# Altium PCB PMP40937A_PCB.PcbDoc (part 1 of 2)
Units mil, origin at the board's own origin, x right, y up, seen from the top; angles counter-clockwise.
Board outline 1377.95 x 1377.95 mil, 2 copper layers (Top Layer, Bottom Layer), stack 62 mil thick; 90 components, 42 nets, 235 pads, 300 vias.
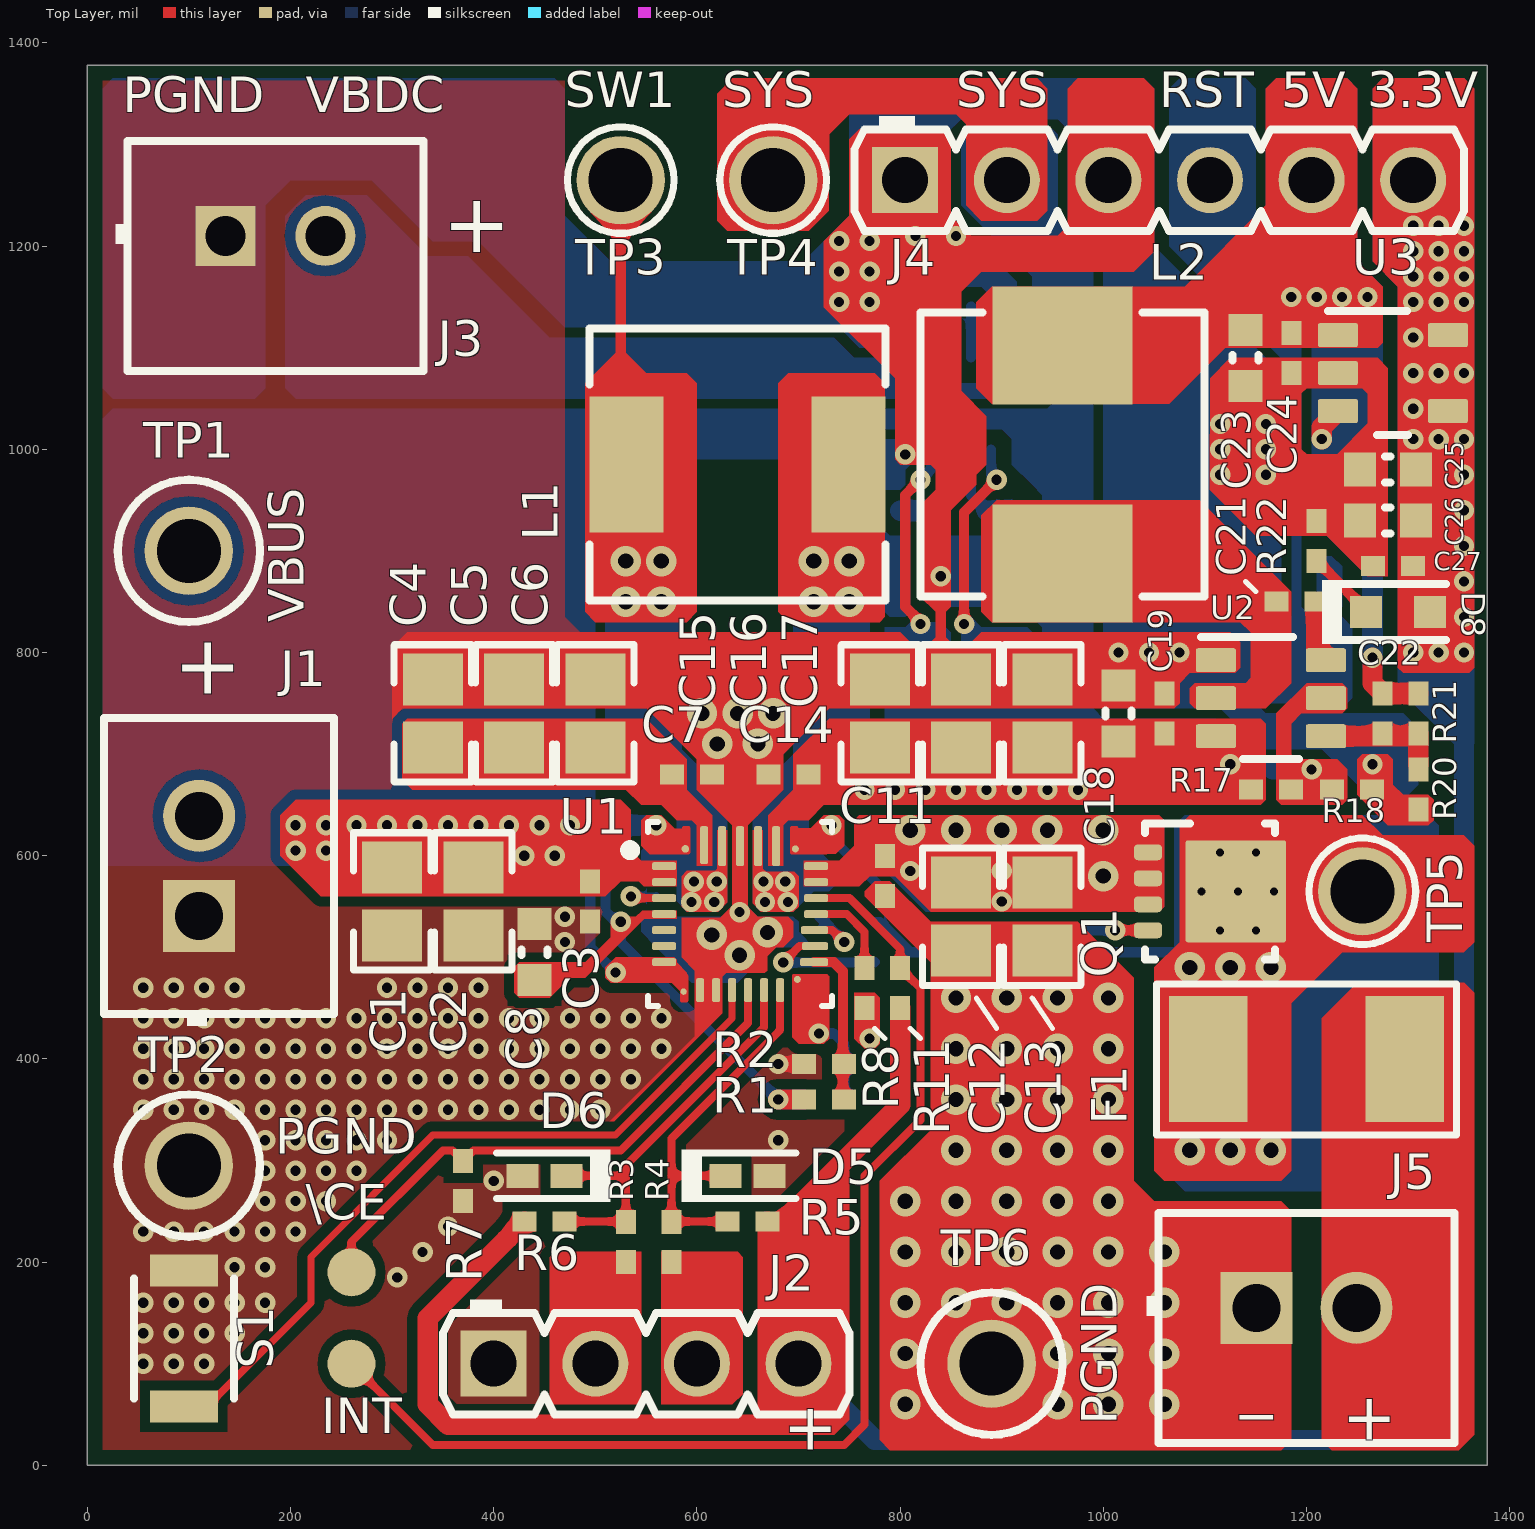
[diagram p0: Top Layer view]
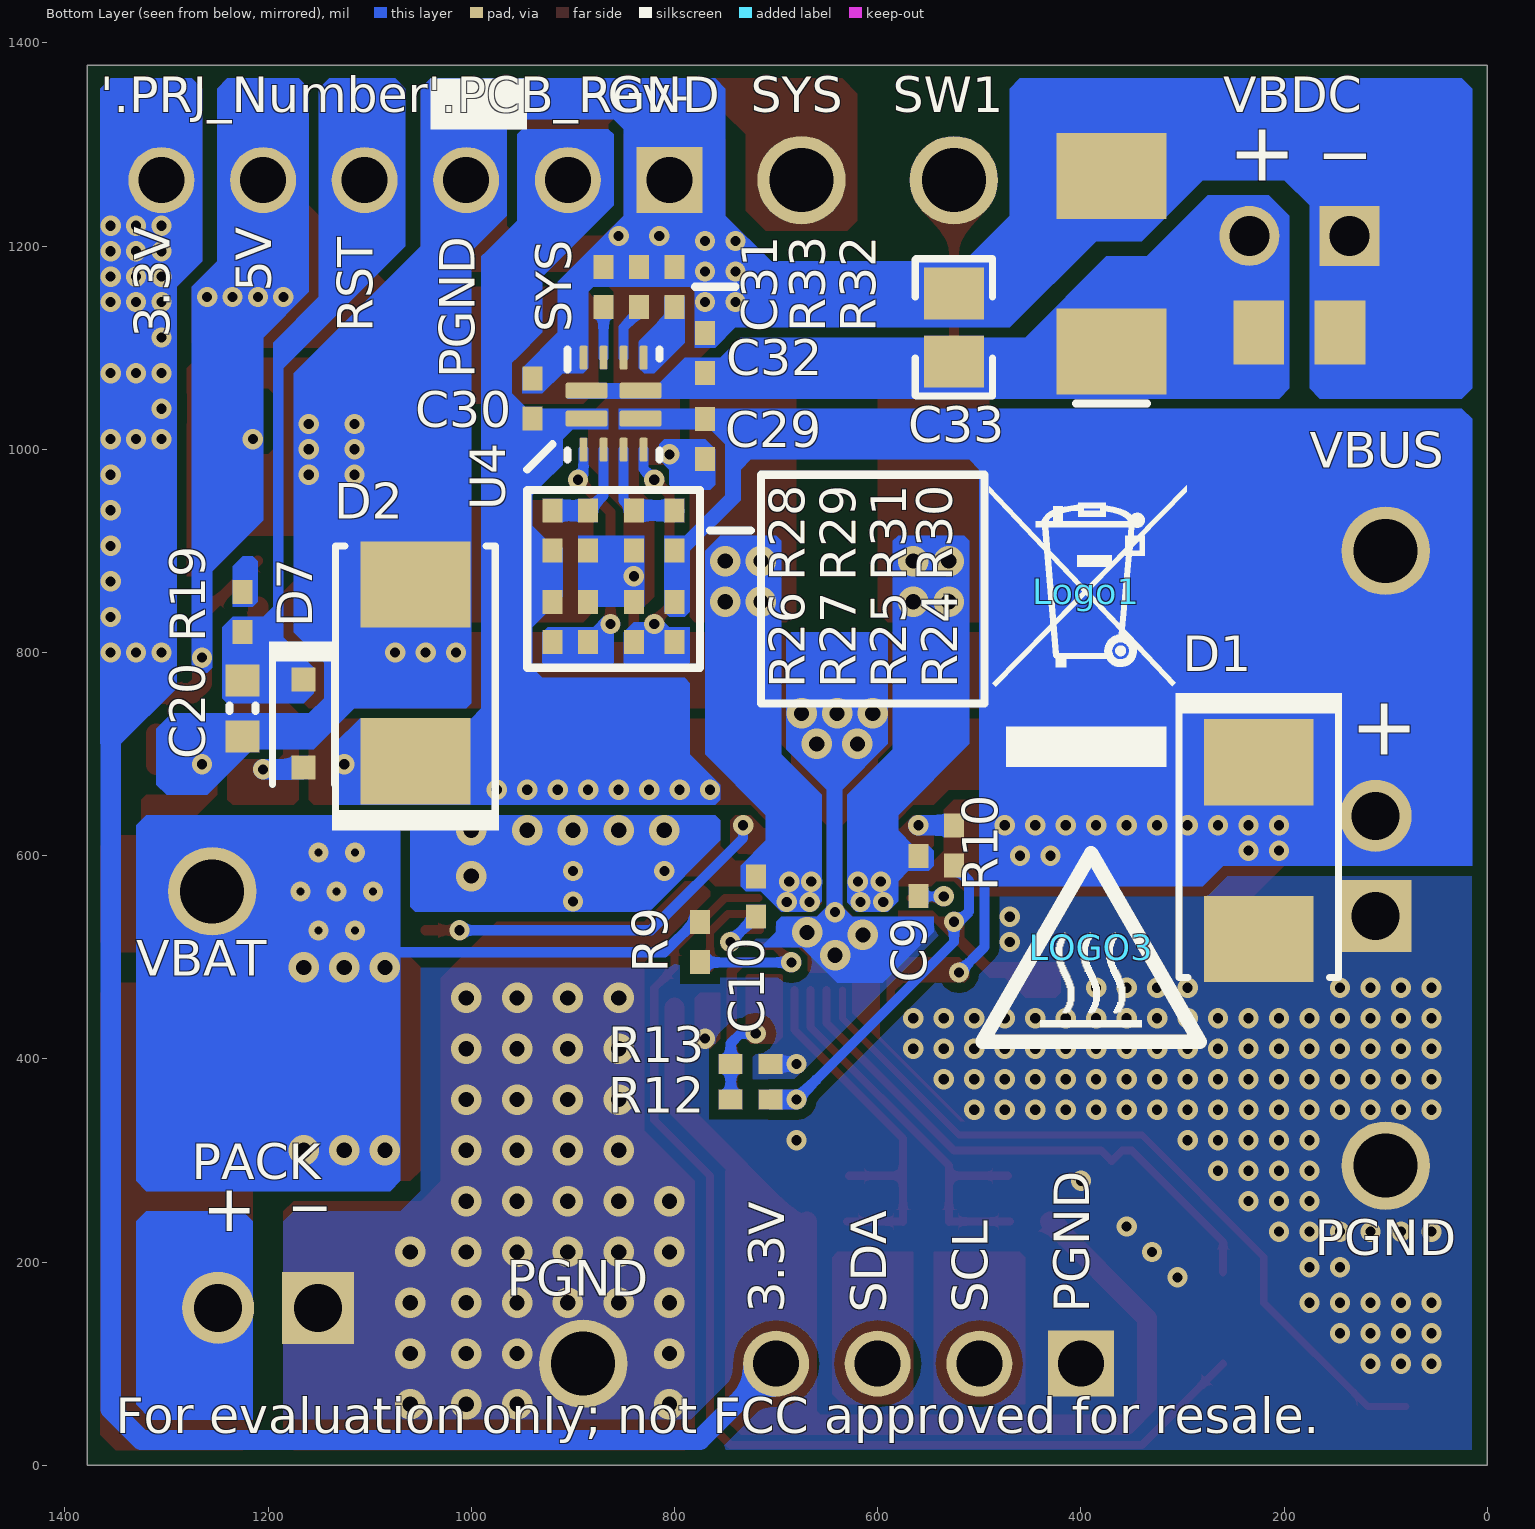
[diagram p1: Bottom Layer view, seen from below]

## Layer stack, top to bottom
Top Solder: solder mask 0.4, Solder Resist, Dk 3.5
Top Layer: signal copper 1.4
Dielectric1: core 59.2, FR-4, Dk 4.8
Bottom Layer: signal copper 1.4
Bottom Solder: solder mask 0.4, Solder Resist, Dk 3.5

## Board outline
0,0 1377.95,0 1377.95,1377.95 0,1377.95

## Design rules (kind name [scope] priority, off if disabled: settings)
AcuteAngle [All] p1: minimum=4.50000000000000E+0001 checktracksonly=FALSE
AssemblyTestPointUsage [All] p1: valid=2
BoardOutlineClearance [OnCopper and Not InComponentClass('Logo') and not InComponentClass('FiducialMark') and not InRegion(1000,500,4000,800)] p1: gap=15 ignorepadtopadclearanceinfootprint=FALSE
BoardOutlineClearance BoardOutlineClearance_MountingHoles [OnCopper and InComponentClass('Mounting Holes')] p2: gap=40 ignorepadtopadclearanceinfootprint=FALSE
BoardOutlineClearance BoardOutlineClearance_Poly [OnCopper and (  InNamedPolygon('Bottom Layer-AGND') or  InNamedPolygon('Signal Layer 1-PGND') or  InNamedPolygon('Signal Layer 2-AGND') or   InNamedPolygon('Top Layer-PGND') )] p3: gap=25 ignorepadtopadclearanceinfootprint=FALSE
Clearance Clearance_FID [IsPad and InComponentClass('FiducialMark') vs IsKeepOut and InComponentClass('FiducialMark')] p1: gap=0 ignorepadtopadclearanceinfootprint=FALSE
Clearance Clearance_2 [InNamedPolygon('Signal Layer 2 - AGND') or InNamedPolygon('Top Layer-PGND')] p2 off: gap=10 ignorepadtopadclearanceinfootprint=FALSE except(0: Arc-Hole Track-Hole SMDPad-Hole THPad-Hole Via-Hole Fill-Hole Poly-Hole Region-Hole Text-Hole; 25: Fill-Fill Fill-Poly Fill-Region Poly-Poly Poly-Region Region-Region)
Clearance "Poly Clearance" [InNamedPolygon('Signal Layer 1-PGND') Or  InNamedPolygon('Top Layer-PGND') Or  InNamedPolygon('Bottom Layer-AGND') Or  InNamedPolygon('Signal Layer 2-AGND')] p3 off: gap=10 ignorepadtopadclearanceinfootprint=FALSE except(0: Arc-Hole Track-Hole SMDPad-Hole THPad-Hole Via-Hole Fill-Hole Poly-Hole Region-Hole Text-Hole)
Clearance Clearance_U1_Top [TouchesRoom('U1_CSP_Top')] p4: gap=2.5 ignorepadtopadclearanceinfootprint=TRUE except(0: Arc-Hole Track-Hole SMDPad-Hole THPad-Hole Via-Hole Fill-Hole Poly-Hole Region-Hole Text-Hole)
Clearance Clearance_U1_Bottom [TouchesRoom('U1_CSP_Bottom')] p5: gap=2.5 ignorepadtopadclearanceinfootprint=TRUE except(0: Arc-Hole Track-Hole SMDPad-Hole THPad-Hole Via-Hole Fill-Hole Poly-Hole Region-Hole Text-Hole)
Clearance Clearance_1 [InNamedPolygon('Signal Layer 2-AGND') or InNamedPolygon('Bottom Layer-AGND') or  InNamedPolygon('Top Layer-PGND') or InNamedPolygon('Signal Layer 1-PGND')] p6 off: gap=10 ignorepadtopadclearanceinfootprint=FALSE except(0: Arc-Hole Track-Hole SMDPad-Hole THPad-Hole Via-Hole Fill-Hole Poly-Hole Region-Hole Text-Hole)
Clearance Stitching [IsStitchingVia and (  InNet('SYS') or   InNet('NetJ2_2') or   InNet('NetJ4_3') or  InNet('BAT') or   InNet('PMID') or  InNet('NetQ1_3') or   InNet('VBOOST') or  InNet('VAC_VBUS') or   InNet('VIN') or  InNet('PGND') or  InNet('AGND') ) vs (IsVia and (Not IsStitchingVia)) Or IsTrack Or IsPadHoleValid] p7 off: gap=15 ignorepadtopadclearanceinfootprint=FALSE except(10: Arc-Via Track-Via THPad-Via)
Clearance Clearance_Keepouts [((IsTrack Or IsArc) And Not InPoly) And IsFree and IsKeepOut vs ((IsTrack Or IsArc) And Not InPoly) And IsFree and IsKeepOut] p8: gap=0 ignorepadtopadclearanceinfootprint=FALSE
Clearance Clearance_Poly [InPolygon] p9: gap=10 ignorepadtopadclearanceinfootprint=FALSE except(0: Arc-Hole Track-Hole SMDPad-Hole THPad-Hole Via-Hole Fill-Hole Poly-Hole Region-Hole Text-Hole)
Clearance [All] p10: gap=5 ignorepadtopadclearanceinfootprint=FALSE
ComponentClearance ComponentClearance_Inductors [HasFootprint('MPIM252010F') vs HasFootprint('SPM6530')] p1: gap=0 collisioncheckmode=3 verticalgap=0 showdistances=FALSE
ComponentClearance ComponentClearance_EMI_Diodes [InComponent('D1') or InComponent('D2')] p2: gap=5 collisioncheckmode=3 verticalgap=10 showdistances=FALSE
ComponentClearance ComponentClearance_Shunt2 [InComponentClass('Shunt') vs InComponentClass('Shunt')] p3: gap=0 collisioncheckmode=3 verticalgap=0 showdistances=FALSE
ComponentClearance ComponentClearance_JP13-14 [InComponent('JP13') vs InComponent('JP14')] p4: gap=0 collisioncheckmode=3 verticalgap=0 showdistances=FALSE
ComponentClearance ComponentClearance_NT [InComponent('NT1')] p5: gap=0 collisioncheckmode=3 verticalgap=0 showdistances=FALSE
ComponentClearance ComponentClearance_MountingHoles_FiducialMarks [InComponentClass('Mounting Holes') or InComponentClass('FiducialMark') vs InComponentClass('FiducialMark')] p6: gap=50 collisioncheckmode=3 verticalgap=10 showdistances=FALSE
ComponentClearance ComponentClearance_MountingHoles [InComponentClass('Mounting Holes')] p7: gap=250 collisioncheckmode=3 verticalgap=100000 showdistances=FALSE
ComponentClearance ComponentClearance_Shunt_1 [InComponentClass('Header') vs InComponentClass('Shunt')] p8: gap=0 collisioncheckmode=3 verticalgap=0 showdistances=FALSE
ComponentClearance ComponentClearance_Logo [InComponentClass('Logo')] p9: gap=0 collisioncheckmode=3 verticalgap=0 showdistances=FALSE
ComponentClearance ComponentClearance_ScrewToNut [(HasFootprint('NY PMS 440 0025 PH')) vs (HasFootprint('Keystone_1902C'))] p10: gap=5 collisioncheckmode=3 verticalgap=10 showdistances=FALSE
ComponentClearance ComponentClearance_SmallPassives [HasFootprint('0201*') or HasFootprint('0402*') or HasFootprint('0508') or HasFootprint('0603*') or HasFootprint('0612') or HasFootprint('0805*') or HasFootprint('0815*') or HasFootprint('0830*') or HasFootprint('1206*') or HasFootprint('1210*') or HasFootprint('1808*') or HasFootprint('1812*') or HasFootprint('1825*') or HasFootprint('2010*') or HasFootprint('2220*') or HasFootprint('2225*') or HasFootprint('2512*') or HasFootprint('2728*') or HasFootprint('3518*') vs HasFootprint('0201*') or HasFootprint('0402*') or HasFootprint('0508') or HasFootprint('0603*') or HasFootprint('0612') or HasFootprint('0805*') or HasFootprint('0815*') or HasFootprint('0830*') or HasFootprint('1206*') or HasFootprint('1210*') or HasFootprint('1808*') or HasFootprint('1812*') or HasFootprint('1825*') or HasFootprint('2010*') or HasFootprint('2220*') or HasFootprint('2225*') or HasFootprint('2512*') or HasFootprint('2728*') or HasFootprint('3518*')] p11: gap=10 collisioncheckmode=3 verticalgap=10 showdistances=FALSE
ComponentClearance ComponentClearance_THtoSMT [IsThruComponent vs IsSMTComponent] p12: gap=20 collisioncheckmode=3 verticalgap=20 showdistances=FALSE
ComponentClearance ComponentClearance_THtoTH [IsThruComponent vs IsThruComponent] p13: gap=30 collisioncheckmode=3 verticalgap=30 showdistances=FALSE
ComponentClearance ComponentClearance_1 [All] p14: gap=10 collisioncheckmode=3 verticalgap=10 showdistances=FALSE
DiffPairsRouting [All] p1: maxlimit=100 minlimit=10 mostfreqgap=10 toplayer_minwidth=15 toplayer_maxwidth=15 toplayer_prefwidth=15 bottomlayer_minwidth=15 bottomlayer_maxwidth=15 bottomlayer_prefwidth=15 maxuncoupledlength=1000
FabricationTestPointUsage TestPointUsage [All] p1: valid=2 allowmultiple=FALSE
FabricationTestpoint Testpoint [All] p1: side=3 testpointundercomponent=TRUE minsize=40 maxsize=100 preferedsize=60 minholesize=0 maxholesize=40 preferedholesize=32 testpointgrid=1 allowsidetop=TRUE allowsidebottom=TRUE usegrid=TRUE gridtolerance=0.01
FanoutControl Fanout_LCC [IsLCC] p1: bgadir=Out bgaviamode=Centered fanoutstyle=Auto fanoutdirection=Alternating viagrid=1 // Fanout_LCC (Default Rule)
FanoutControl Fanout_BGA [IsBGA] p2: bgadir=Out bgaviamode=Centered fanoutstyle=Auto fanoutdirection=Alternating viagrid=1 // Fanout_BGA (Default Rule)
FanoutControl Fanout_Default [All] p4: bgadir=Out bgaviamode=Centered fanoutstyle=Auto fanoutdirection=Alternating viagrid=1 // Fanout_Default (Default Rule)
FanoutControl Fanout_Small [(CompPinCount < 5)] p5: bgadir=Out bgaviamode=Centered fanoutstyle=Auto fanoutdirection=OutThenIn viagrid=1 // Fanout_Small (Default Rule)
HoleSize [All] p1: absolutevalues=TRUE maxlimit=251 minlimit=6 maxpercent=80.000 minpercent=20.000
HoleToHoleClearance [All] p1: gap=9.7 allowstackedmicrovias=TRUE
MinimumAnnularRing MinimumAnnularRing_1 [IsVia AND (WithinRoom('U1_CSP_Top') or WithinRoom('U1_CSP_Bottom'))] p1: minimumring=2
MinimumAnnularRing MinimumAnnularRing_ThermalPadVias [IsVia and InAnyComponent] p2: minimumring=5.91
MinimumAnnularRing [All] p3: minimumring=2
MinimumSolderMaskSliver MinimumSolderMaskSliver_1 [TouchesRoom('U1_CSP_Bottom') or TouchesRoom('U1_CSP_Top')] p1: minsoldermaskwidth=1
MinimumSolderMaskSliver MinimumSolderMaskSliver_Logo [InComponentClass('Logo') vs InComponentClass('Logo')] p2: minsoldermaskwidth=0.7
MinimumSolderMaskSliver [All] p3: minsoldermaskwidth=3.7
PlaneConnect [All] p1: planeconnectstyle=Direct reliefexpansion=10 reliefentries=4 reliefconductorwidth=10 reliefairgap=10
PolygonConnect PolygonConnect_402L [All] p1: connectstyle=Direct reliefconductorwidth=10 reliefentries=4 polygonreliefangle="90 Angle" airgapwidth=10
PolygonConnect PolygonConnect_603L [All] p2: connectstyle=Direct reliefconductorwidth=10 reliefentries=4 polygonreliefangle="90 Angle" airgapwidth=10
RoutingVias RoutingVias_1 [All] p1: holewidth=10 width=20 viastyle="Through Hole" minholewidth=6 minwidth=10 maxholewidth=28 maxwidth=50
RoutingVias ThermalPadVias [IsVia and InAnyComponent] p2: holewidth=7.87 width=19.68 viastyle="Through Hole" minholewidth=7.87 minwidth=19.68 maxholewidth=12.99 maxwidth=23.62
RoutingVias [WithinRoom('U1_CSP')] p3: holewidth=10 width=22 viastyle="Through Hole" minholewidth=2.5 minwidth=5 maxholewidth=40 maxwidth=65
SilkToBoardRegionClearance [Not ((IsComment or IsDesignator) And (Hide <> 'False')) and not InRegion(1000,500,4000,800)] p1:
SilkToSilkClearance SilkToSilkClearance_Pb-FreeLogo [(HasFootprint('Pb-Free_Overlay_Medium') OR HasFootprint('Pb-Free_Overlay_Small')) vs (HasFootprint('Pb-Free_Overlay_Medium') OR HasFootprint('Pb-Free_Overlay_Small'))] p1: silktosilkclearance=0
SilkToSilkClearance [All] p2: silktosilkclearance=1
SilkToSolderMaskClearance [InComponent('L2') vs IsVia] p1: minsilkscreentomaskgap=0 clearancetoexposedcopper=TRUE
SilkToSolderMaskClearance SilkToComponentPadClearance [IsPad and InAnycomponent] p2: minsilkscreentomaskgap=3 clearancetoexposedcopper=TRUE
SilkToSolderMaskClearance "Silk to Solder Mask Opening" [All] p3: minsilkscreentomaskgap=1.7 clearancetoexposedcopper=FALSE
SolderMaskExpansion [All] p1: expansion=1.97
Width [All] p1: maxlimit=100 minlimit=6 preferedwidth=10 checkconnectedcopper=TRUE
14 further rules are at their usual default settings.

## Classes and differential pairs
component class Header: J2 J4

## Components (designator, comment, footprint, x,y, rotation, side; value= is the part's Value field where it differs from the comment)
C1 "CL21A106KAFN3NE" 0805 300,555 r270 top value=10uF
C2 "CL21A106KAFN3NE" 0805 380,555 r270 top value=10uF
C3 "GRM155R71H104ME14D" 0402L 495,555 r90 top value=0.1uF
C4 "CL21A106KAFN3NE" 0805 340,740 r90 top value=10uF
C5 "CL21A106KAFN3NE" 0805 420,740 r90 top value=10uF
C6 "CL21A106KAFN3NE" 0805 500,740 r90 top value=10uF
C7 "GRM155R71H104ME14D" 0402L 595,680 r0 top value=0.1uF
C8 "GRM188R61C475KAAJ" 0603L 440,505 r270 top value=4.7uF
C9 "GRM155R71E473KA88D" 0402L 560,580 r270 bottom value=0.047uF
C10 "GRM155R71E473KA88D" 0402L 720,560 r270 bottom value=0.047uF
C11 "GRM155R71H104ME14D" 0402L 785,580 r270 top value=0.1uF
C12 "CL21A106KAFN3NE" 0805 860,540 r270 top value=10uF
C13 "CL21A106KAFN3NE" 0805 940,540 r270 top value=10uF
C14 "GRM155R71H104ME14D" 0402L 690,680 r180 top value=0.1uF
C15 "CL21A106KAFN3NE" 0805 780,740 r90 top value=10uF
C16 "CL21A106KAFN3NE" 0805 860,740 r90 top value=10uF
C17 "CL21A106KAFN3NE" 0805 940,740 r90 top value=10uF
C18 "GRM188R61E106MA73D" 0603L 1015,740 r90 top value=10uF
C19 "GRM155R71H104ME14D" 0402L 1060,740 r90 top value=0.1uF
C20 "GRM188R61E106MA73D" 0603L 1225,745 r270 bottom value=10uF
C21 "GRM155R71H104ME14D" 0402L 1190,850 r0 top value=0.1uF
C22 "GRM1555C1H100FA01D" 0402L 1275,740 r270 top value=10pF
C23 "GRM188R61E106MA73D" 0603L 1140,1090 r270 top value=10uF
C24 "GRM155R71H104ME14D" 0402L 1185,1095 r90 top value=0.1uF
C25 "GRM188R61E106MA73D" 0603L 1280,980 r180 top value=10uF
C26 "GRM188R61E106MA73D" 0603L 1280,930 r180 top value=10uF
C27 "GRM155R71H104ME14D" 0402L 1285,885 r0 top value=0.1uF
C29 "GRM155R71H104ME14D" 0402L 770,1010 r270 bottom value=0.1uF
C30 "GRM155R71H104ME14D" 0402L 940,1050 r90 bottom value=0.1uF
C31 "GRM155R71H104ME14D" 0402L 870,1160 r270 bottom value=0.1uF
C32 "GRM155R71H104ME14D" 0402L 770,1095 r270 bottom value=0.1uF
C33 "CL21A106KAFN3NE" 0805 525,1120 r90 bottom value=10uF
D1 "SMBJ20CA" SMB 225,605 r270 bottom value=19V
D2 "SMBJ20CA" SMB 1055,780 r90 bottom value=19V
D5 "BZT52C5V6T-7" SOD-523 650,285 r0 top value=5.6V
D6 "BZT52C5V6T-7" SOD-523 450,285 r180 top value=5.6V
D7 "BAS316,115" SOD-323 1165,730 r270 bottom value=100V
D8 "150060RS75000" WL-SMCW_RED 1290,840 r0 top value=Red
F1 "0452005.MRL" SloBlo452 1200,400 r180 top
J1 "B2B-XH-A(LF)(SN)" JST_B2B-XH-A#1 110,590 r90 top
J2 "61300411121" WURTH_61300411121 550,100 r0 top
J3 "B2B-XH-A(LF)(SN)" JST_B2B-XH-A#2 185,1210 r0 top
J4 "61300611121" WURTH_61300611121 1055,1265 r0 top
J5 "B2B-XH-A(LF)(SN)" JST_B2B-XH-A#1 1200,155 r0 top
L1 "SPM6530T-2R2M" SPM6530 640,985 r180 top value=2.2uH
L2 "74437346220" WE-LHMI_7030 960,995 r90 top value=22uH
Logo1 "WEEE logo" WEEE_Minimum 395,860 r180 bottom
Logo2 "FCC disclaimer" FCC_disclaimer 2455,135 r90 bottom
LOGO3 "CAUTION HOT SURFACE" IEC_HotSurface_Small 390,510 r180 bottom
Q1 "CSD17581Q3A" DNH0008A 1105,565 r0 top value=30V
R1 "CRCW040210K0FKED" 0402L 725,360 r180 top value=10.0k
R2 "CRCW040210K0FKED" 0402L 725,395 r0 top value=10.0k
R3 "RC0402FR-07100RL" 0402L 530,220 r90 top value=100
R4 "RC0402FR-07100RL" 0402L 575,220 r90 top value=100
R5 "CRCW040210K0JNED" 0402L 650,240 r180 top value=10k
R6 "CRCW040210K0JNED" 0402L 450,240 r0 top value=10k
R7 "RC0402FR-07100KL" 0402L 370,280 r270 top value=100k
R8 "CRCW040227K0JNED" 0402L 765,470 r270 top value=27k
R9 "RC0402FR-071KL" 0402L 775,515 r90 bottom value=1.00k
R10 "CRCW040210K0FKED" 0402L 525,610 r90 bottom value=10.0k
R11 "RC0402FR-07100KL" 0402L 800,470 r90 top value=100k
R12 "CRCW0402100KFKED" 0402L 725,360 r180 bottom value=100k
R13 "CRCW0402100KFKED" 0402L 725,395 r0 bottom value=100k
R17 "CRCW0402100KFKED" 0402L 1165,665 r180 top value=100k (schematic designator R18)
R18 "CRCW040215K0FKED" 0402L 1245,665 r180 top value=15.0k (schematic designator R19)
R19 "RC0402FR-07100KL" 0402L 1225,840 r270 bottom value=100k (schematic designator R20)
R20 "CRCW040220K0JNED" 0402L 1310,665 r90 top value=20k (schematic designator R21)
R21 "CRCW0402150KFKED" 0402L 1310,740 r270 top value=150k (schematic designator R22)
R22 "RC0402FR-072K2L" 0402L 1210,910 r90 top value=2.20k (schematic designator R23)
R24 "CRCW0402150KFKED" 0402L 800,830 r270 bottom value=150k
R25 "CRCW040210K0FKED" 0402L 840,830 r90 bottom value=10.0k
R26 "CRCW0402169KFKED" 0402L 920,830 r270 bottom value=169k
R27 "CRCW040210K0FKED" 0402L 885,830 r90 bottom value=10.0k
R28 "CRCW0402169KFKED" 0402L 920,920 r270 bottom value=169k
R29 "CRCW040210K0FKED" 0402L 885,920 r90 bottom value=10.0k
R30 "CRCW0402200KFKED" 0402L 800,920 r90 bottom value=200k
R31 "CRCW040210K0FKED" 0402L 840,920 r90 bottom value=10.0k
R32 "CRCW04020000Z0ED" 0402L 800,1160 r270 bottom value=0
R33 "CRCW040243K0JNED" 0402L 835,1160 r270 bottom value=43k
S1 "B3U-1100P" SW_B3U-1000P 95,125 r270 top
TP1 "5010" Keystone5010 100,900 r90 top
TP2 "5011" Keystone5011 100,295 r90 top
TP3 "5002" Keystone5002 525,1265 r180 top
TP4 "5002" Keystone5002 675,1265 r180 top
TP5 "5000" Keystone5000 1255,565 r90 top
TP6 "5011" Keystone5011 890,100 r0 top
U1 "BQ25672RQM" RQM0029A-MFG 642.5,542.5 r0 top
U2 "TPS54302DDCR" DDC0006A_N 1165,755 r0 top
U3 "TLV73333PQDBVRQ1" DBV0005A_N 1285,1075 r0 top
U4 "TPS2121RUXR" RUX0012A 860,1045 r180 bottom

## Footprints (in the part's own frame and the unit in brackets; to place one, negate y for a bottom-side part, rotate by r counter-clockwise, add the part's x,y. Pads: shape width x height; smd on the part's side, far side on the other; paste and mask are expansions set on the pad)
0402L [mm] "0402 from SM-752 data"
  rect 0.6x0.5 smd: 1(-0.5,0) 2(0.5,0)
  body extent -0.55,-0.3 0.55,0.3, height 0.6
0603L [mm] "0603 from SM-752 data"
  rect 0.8x0.85 smd: 1(-0.7,0) 2(0.7,0)
  silkscreen extent -0.07,-0.33 0.07,0.33, body extent -0.87,-0.47 0.87,0.47, height 1
0805 [mm] "0805 from SM-752 data"
  rect 1.3x1.5 smd: 1(-0.85,0) 2(0.85,0)
  silkscreen extent -1.72,-0.97 1.72,0.97, body extent -1.1,-0.72 1.1,0.72, height 1.45
DBV0005A_N [mm] "SOT23, 5-Leads, Body 2.9x1.6mm, Pitch 0.95mm, Lead Span 2.8mm, IPC Medium Density"
  rrect17% 1x0.6 smd: 1(-1.375,0.95) 2(-1.375,0) 3(-1.375,-0.95) 4(1.375,-0.95) 5(1.375,0.95)
  silkscreen extent -1.63,-1.55 0.38,1.55, body extent -1.42,-1.46 1.42,1.46, height 1.09
DDC0006A_N [mm]
  rrect17% 1x0.6 smd: 1(-1.375,0.95) 2(-1.375,0) 3(-1.375,-0.95) 4(1.375,-0.95) 5(1.375,0) 6(1.375,0.95)
  silkscreen extent -1.75,-1.52 0.7,1.53, body extent -1.43,-1.48 1.43,1.49, height 0.92
DNH0008A [mm] "VSONP-8"
  rrect50% 0.7x0.4 smd paste-0.05 mask-0.05: 1(-1.55,0.975) 2(-1.55,0.325) 3(-1.55,-0.325) 4(-1.55,-0.975) 5(1.55,-0.975) 6(1.55,-0.325) 7(1.55,0.325) 8(1.55,0.975)
  rrect4% 2.51x2.55 smd paste-1.5 mask-1.5: 9(0.645,0)
  rrect14% 0.705x1.125 on Top Paste: 9A(-0.208,0.662) 9B(0.697,0.662) 9C(-0.208,-0.663) 9D(0.697,-0.663)
  silkscreen extent -1.62,-1.7 1.62,1.7, body extent -1.65,-1.65 1.65,1.66, height 0.91
FCC_disclaimer [mil]
IEC_HotSurface_Small [mil]
  silkscreen extent -107,-93 107,92
JST_B2B-XH-A#1 [mm] "Header (Shrouded), 2.5mm, 2x1, TH"
  rect 1.8x1.8 hole 1.2: 1(-1.25,0)
  round 1.8 hole 1.2: 2(1.25,0)
  silkscreen extent -4,-3.37 3.7,2.38, body extent -3.7,-3.37 3.7,2.38, height 7
JST_B2B-XH-A#2 [mm] "Header (Shrouded), 2.5mm, 2x1, TH"
  rect 1.5x1.5 hole 1: 1(-1.25,0)
  round 1.5 hole 1: 2(1.25,0)
  silkscreen extent -4,-3.37 3.7,2.38, body extent -3.7,-3.37 3.7,2.38, height 7
Keystone5000 [mil] "For Keystone 500x miniature loop terminals"
  round 87 hole 63: 1(0,0)
  silkscreen extent -52,-52 52,52, body extent -49,-49 49,49, height 182
Keystone5002 [mil] "For Keystone 500x miniature loop terminals"
  round 87 hole 63: 1(0,0)
  silkscreen extent -52,-52 52,52, body extent -49,-49 49,49, height 182
Keystone5010 [mil] "Keystone Multipurpose loops"
  round 87 hole 63: 1(0,0)
  silkscreen extent -70,-70 70,70, body extent -63,-63 63,62, height 319
Keystone5011 [mil] "Keystone Multipurpose loops"
  round 87 hole 63: 1(0,0)
  silkscreen extent -70,-70 70,70, body extent -63,-63 63,62, height 319
RQM0029A-MFG [mm]
  round 0.192 smd paste+0 mask+0: 1(-1.369,1.631)
  rrect50% 0.6x0.2 smd paste+0 mask+0: 2(-1.9,1.2) 3(-1.9,0.8) 4(-1.9,0.4) 5(-1.9,0) 6(-1.9,-0.4) 7(-1.9,-0.8) 8(-1.9,-1.2) 20(1.9,0) 21(1.9,0.4) 22(1.9,0.8) 23(1.9,1.2)
  round 0.158 smd paste+0 mask+0: 9(-1.412,-1.937)
  rrect50% 0.2x0.6 smd paste+0 mask+0: 10(-1,-1.9) 11(-0.6,-1.9) 12(-0.2,-1.9) 13(0.2,-1.9) 14(0.6,-1.9) 15(1,-1.9)
  round 0.175 smd paste+0 mask+0: 16(1.431,-1.631) 24(1.381,1.631)
  rrect50% 0.7x0.2 smd paste+0 mask+0: 17(1.85,-1.2)
  rrect50% 0.65x0.2 smd paste+0 mask+0: 18(1.875,-0.8)
  rrect50% 0.68x0.2 smd paste+0 mask+0: 19(1.86,-0.4)
  rrect50% 0.2x1 smd paste+0 mask+0: 25(0.9,1.7) 26(0.45,1.7) 27(0,1.7) 28(-0.45,1.7)
  rrect50% 0.2x0.95 smd paste+0 mask+0: 29(-0.9,1.725)
  Top Layer region: 2.2,1.65 2.196,1.669 2.185,1.685 2.169,1.696 2.15,1.7 2.15,1.7 1.45,1.7 1.45,2.15 1.446,2.169 1.435,2.185 1.419,2.196 1.4,2.2 1.4,2.2 1.3,2.2 1.275,2.193 1.257,2.175 1.25,2.15 1.25,2.15 1.25,1.55 1.254,1.531 1.265,1.515 1.281,1.504 1.3,1.5 1.3,1.5 2.15,1.5 2.169,1.504 2.185,1.515 2.196,1.531 2.2,1.55 2.2,1.55
  Top Layer region: 2.2,-1.65 2.193,-1.675 2.175,-1.693 2.15,-1.7 2.15,-1.7 1.5,-1.7 1.5,-2.15 1.496,-2.169 1.485,-2.185 1.469,-2.196 1.45,-2.2 1.45,-2.2 1.35,-2.2 1.325,-2.193 1.307,-2.175 1.3,-2.15 1.3,-2.15 1.3,-1.55 1.304,-1.531 1.315,-1.515 1.331,-1.504 1.35,-1.5 1.35,-1.5 2.15,-1.5 2.169,-1.504 2.185,-1.515 2.196,-1.531 2.2,-1.55 2.2,-1.55
  Top Layer region: -2.2,-1.65 -2.193,-1.675 -2.175,-1.693 -2.15,-1.7 -2.15,-1.7 -1.5,-1.7 -1.5,-2.15 -1.496,-2.169 -1.485,-2.185 -1.469,-2.196 -1.45,-2.2 -1.45,-2.2 -1.35,-2.2 -1.331,-2.196 -1.315,-2.185 -1.304,-2.169 -1.3,-2.15 -1.3,-2.15 -1.3,-1.55 -1.304,-1.531 -1.315,-1.515 -1.331,-1.504 -1.35,-1.5 -1.35,-1.5 -2.15,-1.5 -2.169,-1.504 -2.185,-1.515 -2.196,-1.531 -2.2,-1.55 -2.2,-1.55
  Top Layer region: -2.2,1.65 -2.193,1.675 -2.175,1.693 -2.15,1.7 -2.15,1.7 -1.45,1.7 -1.45,2.15 -1.443,2.175 -1.425,2.193 -1.4,2.2 -1.4,2.2 -1.3,2.2 -1.275,2.193 -1.257,2.175 -1.25,2.15 -1.25,2.15 -1.25,1.55 -1.254,1.531 -1.265,1.515 -1.281,1.504 -1.3,1.5 -1.3,1.5 -2.15,1.5 -2.169,1.504 -2.185,1.515 -2.196,1.531 -2.2,1.55 -2.2,1.55
  silkscreen extent -2.87,-2.3 2.3,2.3, body extent -2.3,-2.3 2.3,2.3, height 0.25
RUX0012A [mm] "VQFN-HR-12"
  rrect25% 1.05x0.4 smd: 1(-0.675,0.325) 2(-0.675,-0.375) 7(0.675,-0.375) 8(0.675,0.325)
  rrect40% 0.2x0.6 smd: 3(-0.75,-1.15) 4(-0.25,-1.15) 5(0.25,-1.15) 6(0.75,-1.15) 9(0.75,1.15) 10(0.25,1.15) 11(-0.25,1.15) 12(-0.75,1.15)
  silkscreen extent -1.15,-1.4 1.15,1.35, body extent -1.05,-1.3 1.05,1.3, height 1
SloBlo452 [mm] "Littelfuse 452/4 Fuses, recommended land pattern"
  rect 1.96x3.15 smd: 1(-2.455,0) 2(2.455,0)
  silkscreen extent -3.75,-1.88 3.75,1.9, body extent -3.05,-1.35 3.05,1.34, height 2.69
SMB [mil] "Molded Diode, 2-Leads, Body 5.4x3.6mm, IPC Medium Density, based on OnSemi component dimensions"
  rect 85x107.99 smd: 1(-87.01,0) 2(87.01,0)
  silkscreen extent -155,-82 125,82, body extent -106,-71 106,71, height 91
SOD-323 [mm] "NXP recommended land pattern"
  rect 0.6x0.6 smd paste-0.05: 1(-1.1,0) 2(1.1,0)
  silkscreen extent -2.06,-0.86 1.53,0.86, body extent -1.3,-0.67 1.3,0.68, height 1.1
SOD-523 [mm] "NXP Semiconductor recommended land pattern, nominal STEP model"
  rect 0.8x0.6 smd paste-0.05: 1(-0.55,0) 2(0.55,0)
  silkscreen extent -1.65,-0.66 1.2,0.66, body extent -0.8,-0.4 0.8,0.4, height 0.72
SPM6530 [mm] "TDK"
  rect 1.85x3.4 smd: 1(-2.775,0) 2(2.775,0)
  silkscreen extent -3.7,-3.4 3.7,3.4, body extent -3.7,-3.4 3.7,3.4, height 3.3
SW_B3U-1000P [mm] "OMRON"
  rect 0.8x1.7 smd: 1(-1.7,0) 2(1.7,0)
  silkscreen extent -1.5,-1.25 1.5,1.25, body extent -1.5,-1.25 1.5,1.25, height 1.75
WE-LHMI_7030 [mm] "Wurth"
  rect 2.95x3.5 smd: 1(-2.725,0) 2(2.725,0)
  silkscreen extent -3.55,-3.55 3.55,3.55, body extent -3.8,-3.45 3.8,3.45, height 3
WEEE_Minimum [mil] "WEEElie bin"
  silkscreen extent -95,-172 99,104
WL-SMCW_RED [mm] "WURTH"
  rect 0.8x0.8 smd: 1(-0.8,0) 2(0.8,0)
  silkscreen extent -1.9,-0.8 1.2,0.8, body extent -0.85,-0.45 0.85,0.45, height 0.8
WURTH_61300411121 [mm] "Header, 2.54mm, 4x1, TH"
  rect 1.65x1.65 hole 1.15: 1(-3.81,0)
  round 1.65 hole 1.15: 2(-1.27,0) 3(1.27,0) 4(3.81,0)
  silkscreen extent -5.08,-1.27 5.08,1.6, body extent -5.08,-1.27 5.08,1.27, height 8.54
WURTH_61300611121 [mm] "Header, 2.54mm, 6x1, TH"
  rect 1.65x1.65 hole 1.15: 1(-6.35,0)
  round 1.65 hole 1.15: 2(-3.81,0) 3(-1.27,0) 4(1.27,0) 5(3.81,0) 6(6.35,0)
  silkscreen extent -7.62,-1.27 7.62,1.6, body extent -7.62,-1.27 7.62,1.27, height 8.54

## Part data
C1 C2 C4 C5 C6 C12 C13 C15 C16 C17 C33: "CAP, CERM, 10 µF, 25 V,+/- 10%, X5R, 0805", Cap_Case=0805, Manufacturer="Samsung Electro-Mechanics", Supplier Part Number 1=1276-2890-1-ND, TempCo=X5R, Tolerance_%=10, Value2=25V, ValueDisplayed=10µF
C3 C7 C11 C14 C19 C21 C24 C27 C29 C30 C31 C32: "CAP, CERM, 0.1 µF, 50 V,+/- 20%, X7R, 0402", Cap_Case=0402, Manufacturer=MuRata, Supplier Part Number 1=490-10701-1-ND, TempCo=X7R, Tolerance_%=20, Value2=50V, ValueDisplayed=0.1µF
C8: "CAP, CERM, 4.7 µF, 16 V,+/- 10%, X5R, 0603", Cap_Case=0603, Manufacturer=MuRata, Supplier Part Number 1=490-10481-1-ND, TempCo=X5R, Tolerance_%=10, Value2=16V, ValueDisplayed=4.7µF
C9 C10: library part CMP-0006669-2, "CAP, CERM, 0.047 uF, 25 V, +/- 10%, X7R, 0402", Cap_Case=0402, Manufacturer=MuRata, Supplier Part Number 1=490-3254-1-ND, TempCo=X7R, Tolerance_%=10%, Value1=Unknown, Value2=25V, ValueDisplayed=0.047uF
C18 C20 C23 C25 C26: "CAP, CERM, 10 µF, 25 V,+/- 20%, X5R, 0603", Cap_Case=0603, Manufacturer=MuRata, Supplier Part Number 1=490-7202-1-ND, TempCo=X5R, Tolerance_%=20, Value2=25V, ValueDisplayed=10µF
C22: "CAP, CERM, 10 pF, 50 V,+/- 1%, C0G/NP0, 0402", Cap_Case=0402, Manufacturer=MuRata, Supplier Part Number 1=490-6186-1-ND, TempCo=C0G/NP0, Tolerance_%=1, Value2=50V, ValueDisplayed=10pF
D1 D2: "Diode, TVS, Bi, 19 V, SMB", Manufacturer=Littelfuse, Power_W=5, Supplier Part Number 1=SMBJ20CALFDKR-ND, Value1=5W
D5 D6: "Diode, Zener, 5.6 V, 300 mW, SOD-523", Manufacturer="Diodes Inc.", Power_W=0.3, Supplier Part Number 1=BZT52C5V6TDICT-ND, Value1=0.3W
D7: "Diode, Ultrafast, 100 V, 0.25 A, SOD-323", Manufacturer=Nexperia, Supplier Part Number 1=568-5003-1-ND, Value1=0.25A, Value2=1.4V
D8: "LED, Red, SMD", Color=Red, Manufacturer="Wurth Elektronik", Power_TotalModule=0.072, Supplier Part Number 1=732-4978-1-ND, Value1=0.072W, Value2=2V
F1: "Fuse, 5 A, 125VAC/VDC, SMD", Irating_A=5, Manufacturer=Littelfuse, Supplier Part Number 1=F2607CT-ND
J1 J3 J5: library part CMP-0075223-1, "Header (Shrouded), 2.5mm, 2x1, Tin, TH", Color=White, Current_A=3A, Manufacturer="JST Manufacturing", Supplier Part Number 1=455-2247-ND, Voltage_V=250V
J2: "Header, 2.54 mm, 4x1, Gold, TH", Manufacturer="Wurth Elektronik", Supplier Part Number 1=732-5317-ND
J4: "Header, 2.54 mm, 6x1, Gold, TH", Manufacturer="Wurth Elektronik", Supplier Part Number 1=732-5319-ND
L1: library part CMP-0062870-1, "Inductor, Shielded, Ferrite, 2.2 uH, 8.2 A, 0.019 ohm, SMD", Manufacturer=TDK, Supplier Part Number 1=445-4118-1-ND, Value1="0.019 ohm", Value2=8.2A, ValueDisplayed=2.2uH
L2: library part CMP-0064490-2, "Inductor, Shielded Drum Core, Powdered Iron, 22 uH, 1.9 A, 0.165 ohm, SMD", Manufacturer="Wurth Elektronik", Supplier Part Number 1=732-3380-1-ND, Value1="0.165 ohm", Value2=1.9A, ValueDisplayed=22uH
Logo1: library part CMP-0074769-1
Logo2: library part CMP-0074847-1, "FCC_disclaimer"
LOGO3: library part CMP-0074837-1, "IEC 61010-1 Hot Surface Warning"
Q1: library part CMP-0079500-2, "MOSFET, N-CH, 30 V, 60 A, DNH0008A (VSONP-8)", Alternate Manufacturer=None, Manufacturer="Texas Instruments", Supplier Part Number 1=CSD17581Q3A-ND, Value1="0.0047 ohm", Value2="20 nC"
R1 R2 R10 R25 R27 R29 R31: "RES, 10.0 k, 1%, 0.063 W, 0402", Manufacturer=Vishay-Dale, Power_W=0.063, Supplier Part Number 1=541-10.0KLCT-ND, TempCo="100 ppm/C", Tolerance_%=1, Value1=1%, Value2=0.063W, Value_Code=10k0, ValueDisplayed=10.0k
R3 R4: "RES, 100, 1%, 0.063 W, 0402", Manufacturer="Yageo America", Power_W=0.063, Supplier Part Number 1=311-100LRCT-ND, TempCo="100 ppm/C", Tolerance_%=1, Value1=1%, Value2=0.063W, Value_Code=100R, ValueDisplayed=100
R5 R6: "RES, 10 k, 5%, 0.063 W, 0402", Manufacturer=Vishay-Dale, Power_W=0.063, Supplier Part Number 1=541-10KJCT-ND, TempCo="200 ppm/C", Tolerance_%=5, Value1=5%, Value2=0.063W, Value_Code=10k0, ValueDisplayed=10k
R7 R11: "RES, 100 k, 1%, 0.0625 W, 0402", Manufacturer="Yageo America", Power_W=0.0625, Supplier Part Number 1=311-100KLRCT-ND, TempCo="100 ppm/C", Tolerance_%=1, Value1=1%, Value2=0.0625W, Value_Code=100k
R8: "RES, 27 k, 5%, 0.063 W, 0402", Manufacturer=Vishay-Dale, Power_W=0.063, Supplier Part Number 1=541-27KJCT-ND, TempCo="200 ppm/C", Tolerance_%=5, Value1=5%, Value2=0.063W, Value_Code=27k0, ValueDisplayed=27k
R9: "RES, 1.00 k, 1%, 0.0625 W, 0402", Manufacturer="Yageo America", Power_W=0.0625, Supplier Part Number 1=311-1.00KLRCT-ND, TempCo="100 ppm/C", Tolerance_%=1, Value1=1%, Value2=0.0625W, Value_Code=1k00, ValueDisplayed=1.00k
R12 R13 R17: "RES, 100 k, 1%, 0.063 W, 0402", Manufacturer=Vishay-Dale, Power_W=0.063, Supplier Part Number 1=541-100KLCT-ND, TempCo="100 ppm/C", Tolerance_%=1, Value1=1%, Value2=0.063W, Value_Code=100k
R18: "RES, 15.0 k, 1%, 0.063 W, 0402", Manufacturer=Vishay-Dale, Power_W=0.063, Supplier Part Number 1=541-15.0KLCT-ND, TempCo="100 ppm/C", Tolerance_%=1, Value1=1%, Value2=0.063W, Value_Code=15k0, ValueDisplayed=15.0k
R19: library part CMP-0026721-1, "RES, 100 k, 1%, 0.0625 W, 0402", Manufacturer="Yageo America", Power_W=62.5mW, Supplier Part Number 1=311-100KLRCT-ND, TempCo="100 ppm/C", Tolerance_%=1%, Value2=0.0625W, Value_Code=100k
R20: "RES, 20 k, 5%, 0.063 W, 0402", Manufacturer=Vishay-Dale, Power_W=0.063, Supplier Part Number 1=541-20KJCT-ND, TempCo="200 ppm/C", Tolerance_%=5, Value1=5%, Value2=0.063W, Value_Code=20k0, ValueDisplayed=20k
R21 R24: "RES, 150 k, 1%, 0.063 W, 0402", Manufacturer=Vishay-Dale, Power_W=0.063, Supplier Part Number 1=541-150KLCT-ND, TempCo="100 ppm/C", Tolerance_%=1, Value1=1%, Value2=0.063W, Value_Code=150k
R22: "RES, 2.20 k, 1%, 0.063 W, 0402", Manufacturer="Yageo America", Power_W=0.063, Supplier Part Number 1=311-2.20KLRCT-ND, TempCo="100 ppm/C", Tolerance_%=1, Value1=1%, Value2=0.063W, Value_Code=2k20, ValueDisplayed=2.20k
R26 R28: "RES, 169 k, 1%, 0.063 W, 0402", Manufacturer=Vishay-Dale, Power_W=0.063, Supplier Part Number 1=541-169KLCT-ND, TempCo="100 ppm/C", Tolerance_%=1, Value1=1%, Value2=0.063W, Value_Code=169k
R30: "RES, 200 k, 1%, 0.063 W, 0402", Manufacturer=Vishay-Dale, Power_W=0.063, Supplier Part Number 1=541-200KLCT-ND, TempCo="100 ppm/C", Tolerance_%=1, Value1=1%, Value2=0.063W, Value_Code=200k
R32: "RES, 0, 5%, 0.063 W, 0402", Manufacturer=Vishay-Dale, Power_W=0.063, Supplier Part Number 1=541-0.0JCT-ND, TempCo="200 ppm/C", Tolerance_%=5, Value1=5%, Value2=0.063W, Value_Code=0000, ValueDisplayed=0
R33: "RES, 43 k, 5%, 0.063 W, 0402", Manufacturer=Vishay-Dale, Power_W=0.063, Supplier Part Number 1=541-43KJCT-ND, TempCo="200 ppm/C", Tolerance_%=5, Value1=5%, Value2=0.063W, Value_Code=43k0, ValueDisplayed=43k
S1: library part KSR221GLFS, "Switch, Normally open, 2.3N force, 200k operations, SMD", CurrentRating_mA=1001
TP1: "Test Point, Multipurpose, Red, TH", Color=Red, Manufacturer=Keystone, Supplier Part Number 1=36-5010-ND
TP2 TP6: "Test Point, Multipurpose, Black, TH", Color=Black, Manufacturer=Keystone, Supplier Part Number 1=36-5011-ND
TP3 TP4: library part CMP-0055139-1, "Test Point, Miniature, White, TH", Color=White, Manufacturer=Keystone, Supplier Part Number 1=36-5002-ND
TP5: "Test Point, Miniature, Red, TH", Color=Red, Manufacturer=Keystone, Supplier Part Number 1=36-5000-ND
U1: library part CMP-0091155-2, "I2C Controlled, 1-4 Cell, 5-A Buck Battery Charger with Dual-Input Selector and Integrated ADC", Manufacturer="Texas Instruments", Max Supply Voltage=24V, Min Supply Voltage=3.6V, Operating Temperature Range=to
U2: "4.5-V to 28-V Input, 3-A Output, EMI Friendly Synchronous Step-Down Converter, DDC0006A (SOT-23-T-6)", Alternate Manufacturer="Texas Instruments", Alternate PartNumber=TPS54302DDCT
U3: library part CMP-0860155-1, "Automotive capacitor-free 300-mA LDO regulator with foldback current limit for portable devices, DBV0005A (SOT-23-5)", Alternate Manufacturer="Texas Instruments", Operating Temperature Range="-40 to 125,-40 to 150 C", Rating=Automotive
U4: library part CMP-0078351-3, "2.7V-22V, 4A, 50mohm Priority Power MUX, RUX0012A (VQFN-HR-12)", Alternate Manufacturer="Texas Instruments", Alternate PartNumber=TPS2121RUXT

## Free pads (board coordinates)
  rect 50x63 smd far side: 1(145,1115) 2(225,1115)
  round 47.24 smd: 1(260,190) 2(260,100)
  rect 107.99x85 smd far side: 1(370,1096.26) 2(370,1269.02)

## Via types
v1: diameter 20, hole 10, Top Layer to Bottom Layer, tented both sides, 199 vias
v2: diameter 30, hole 15, Top Layer to Bottom Layer, tented both sides, 63 vias
v3: diameter 20, hole 10, Top Layer to Bottom Layer, tented top, 13 vias
v4: diameter 19.68, hole 7.87, Top Layer to Bottom Layer, 6 vias
v5: diameter 20, hole 10, Top Layer to Bottom Layer, tented bottom, 6 vias
v6: diameter 30, hole 15, Top Layer to Bottom Layer, tented top, 6 vias
v7: diameter 20, hole 10, Top Layer to Bottom Layer, 4 vias
v8: diameter 19.68, hole 7.87, Top Layer to Bottom Layer, tented both sides, 1 vias
v9: diameter 30, hole 15, Top Layer to Bottom Layer, tented bottom, 1 vias
v10: diameter 30, hole 15, Top Layer to Bottom Layer, 1 vias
